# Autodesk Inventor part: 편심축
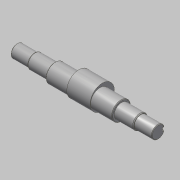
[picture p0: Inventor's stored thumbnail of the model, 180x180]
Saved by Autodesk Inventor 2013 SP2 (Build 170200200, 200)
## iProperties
Created: 2015-10
Part Number: 편심축
Document SubType Name: Modeling
Designer: mdu
Density: 7.86 g/cm^3
Material: 강철, 연강
Mass: 1327.93 g
Surface Area: 248.524 cm^2
Volume: 168.947 cm^3
Author: mdu
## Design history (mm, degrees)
sketch "스케치1"
  geometry: L1 (-20.5, -41.331)-(-20.5, 32.669) reference; L2 (7.5, -30.031)-(7.5, 21.369) reference; L3 (135.5, -30.331)-(135.5, 21.669) reference; L4 (121.5, 21.369)-(121.5, -30.031) reference; L5 (184.5, -4.331)-(-57.5, -4.331); L6 (184.5, -4.331)-(184.5, 6.669); L7 (154.5, 8.169)-(121.5, 8.169); L8 (121.5, 8.169)-(121.5, 11.669); L9 (121.5, 11.669)-(7.5, 11.669); L10 (7.5, 11.669)-(7.5, 8.169); L11 (7.5, 8.169)-(-27.5, 8.169); L12 (-27.5, 8.169)-(-27.5, 6.669); L13 (-27.5, 6.669)-(-57.5, 6.669); L14 (-57.5, 6.669)-(-57.5, -4.331); L15 (154.5, 8.169)-(154.5, 6.669); L16 (154.5, 6.669)-(184.5, 6.669); C1 r 32.5 at (64.5, -4.331) reference; 1 further point
  constraints: 24 end point, 8 perpendicular, 5 point on line, 3 parallel, 2 collinear
  dimensions: "d1" = 25 diameter of L11 L5; "d2" = 32 diameter of L9 L5; "d3" = 22 diameter of L13 L5; "d4" = 35 distance of L10.end L11.end; "d5" = 30 distance of L12.end L13.end; "d15" = 33 distance of L7.start L7.end; "d26" = 30 distance of L15.end L6.end
revolve "회전1" sketch "스케치1" stored, may be unused: angle "d6" = 90 deg
node "작업 평면1"
sketch "스케치2"
  geometry: C1 r 16 at (0, 0) reference; C2 r 16 at (0, 0) reference; C3 r 20.75 at (0, 4); C4 r 16 at (0, 0) reference; 1 further point
  constraints: 1 centre point, 1 vertical alignment
  dimensions: "d8" = 41.5 diameter of C3; "d25" = 4 distance of C3.centre C1.centre
extrude "돌출1" join sketch "스케치2" stored distance "d9" = 40; taper "d10" = 0 deg
chamfer "모따기1" distance "d11" = 1; stored, may be unused: second distance "d12" = 2, angle "d13" = 45 deg
node "작업 평면2"
sketch "스케치3"
  geometry: L1 (-15, -10)-(-15, 10) reference; L2 (-15, 3)-(0, 3); L3 (0, -3)-(-15, -3); A1 r 3 centre (0, 0) between (0, -3) and (0, 3); 2 further points
  constraints: 4 end point, 2 perpendicular, 2 point on circle, 2 point on line, 2 tangent, 1 centre point, 1 horizontal alignment, 1 midpoint
  dimensions: "d16" = 18 dimension on A1 L1; "d17" = 6 distance between parallel lines of L3 L2
extrude "돌출2" cut sketch "스케치3" distance "d18" = 3.5; taper "d19" = 0 deg
node "작업 평면3"
chamfer "모따기2" distance "d27" = 1.5; stored, may be unused: second distance "d28" = 2, angle "d29" = 30 deg
chamfer "모따기3" distance "d30" = 1.5; stored, may be unused: second distance "d31" = 2, angle "d32" = 30 deg
node "솔리드1"
mirror "대칭1"
node "참조1"
node "참조2"
node "참조3"
node "참조4"
node "참조5"
node "투영된 루프1"
